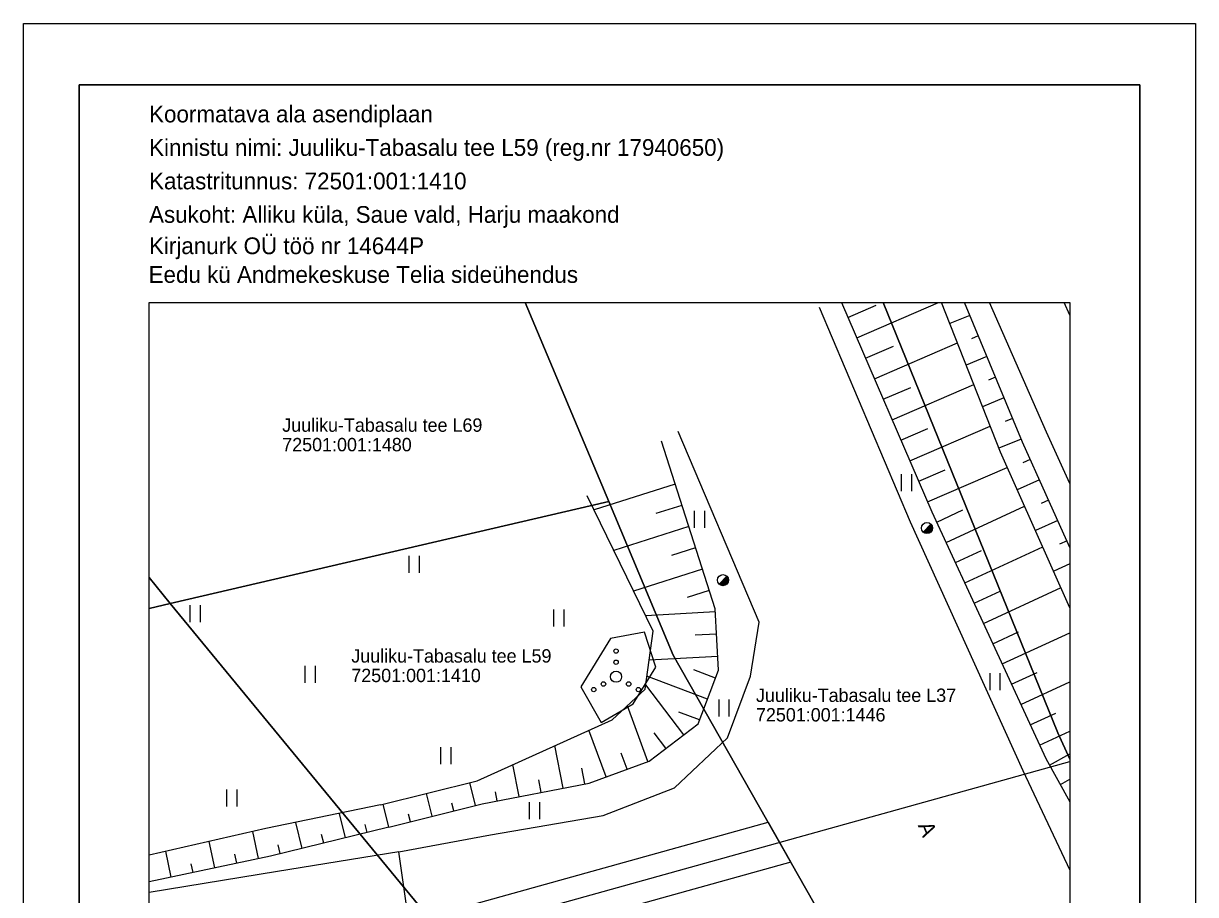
# Model space of a CAD drawing. Extents: x 533265.2 to 533317.7, y 6581481.2 to 6581555.4.
# Drawn here: x 533265.2 to 533317.7, y 6581516.4 to 6581555.4 of the extents above; entities that cross this region are included whole.
import ezdxf

# ---------------------------------------------------------------- set-up
doc = ezdxf.new("R2010")
doc.units = 0
for name, color, linetype in [('HALJASTUS', 7, 'Continuous'), ('KASUTUSALA', 7, 'Continuous'), ('PIIR', 7, 'Continuous'), ('POST', 7, 'Continuous'), ('PR_SIDE', 7, 'Continuous'), ('RELJEEF', 7, 'Continuous'), ('TEE', 7, 'Continuous'), ('VORMISTUS', 7, 'Continuous')]:
    doc.layers.add(name, color=color, linetype=linetype)

msp = doc.modelspace()

# ---------------------------------------------------------------- linework, layer by layer
at = {"layer": 'HALJASTUS'}
for p, q in [((533304.51, 6581535.234), (533304.51, 6581534.473)), ((533304.966, 6581535.234), (533304.966, 6581534.473)), ((533295.237, 6581533.587), (533295.237, 6581532.826)), ((533295.692, 6581533.587), (533295.692, 6581532.826)), ((533282.457, 6581531.581), (533282.457, 6581530.82)), ((533282.912, 6581531.581), (533282.912, 6581530.82)), ((533272.65, 6581529.364), (533272.65, 6581528.603)), ((533273.105, 6581529.364), (533273.105, 6581528.603)), ((533288.939, 6581529.174), (533288.939, 6581528.413)), ((533289.394, 6581529.174), (533289.394, 6581528.413)), ((533277.798, 6581526.641), (533277.798, 6581525.879)), ((533278.253, 6581526.641), (533278.253, 6581525.879)), ((533308.477, 6581526.324), (533308.477, 6581525.563)), ((533308.932, 6581526.324), (533308.932, 6581525.563)), ((533296.334, 6581525.141), (533296.334, 6581524.38)), ((533296.789, 6581525.141), (533296.789, 6581524.38)), ((533283.875, 6581523.009), (533283.875, 6581522.248)), ((533284.33, 6581523.009), (533284.33, 6581522.248)), ((533274.295, 6581521.109), (533274.295, 6581520.347)), ((533274.751, 6581521.109), (533274.751, 6581520.347)), ((533287.852, 6581520.539), (533287.852, 6581519.777)), ((533288.307, 6581520.539), (533288.307, 6581519.777))]:
    msp.add_line(p, q, dxfattribs=at)
msp.add_lwpolyline([(533292.5, 6581524.94), (533293.512, 6581526.593), (533293.016, 6581528.153), (533291.487, 6581527.871), (533290.163, 6581525.701), (533291.07, 6581524.104), (533292.5, 6581524.94)], dxfattribs=at)
for centre, radius in [((533291.738, 6581527.309), 0.1), ((533291.738, 6581526.809), 0.1), ((533291.738, 6581526.159), 0.25), ((533290.738, 6581525.584), 0.1), ((533291.173, 6581525.834), 0.1), ((533292.303, 6581525.834), 0.1), ((533292.738, 6581525.584), 0.1)]:
    msp.add_circle(centre, radius, dxfattribs=at)
at = {"layer": 'KASUTUSALA'}
msp.add_lwpolyline([(533298.55, 6581519.64), (533299.566, 6581517.847), (533284.712, 6581513.713), (533283.321, 6581515.401)], close=True, dxfattribs=at)
at = {"layer": 'PIIR'}
for points in [[(533287.673, 6581542.926), (533291.41, 6581534.01), (533271.76, 6581529.44), (533270.819, 6581530.608)], [(533312.069, 6581495.797), (533303.4, 6581511.09), (533294.3, 6581527.13), (533291.41, 6581534.01), (533287.673, 6581542.926)], [(533312.069, 6581522.468), (533311.52, 6581523.65), (533303.707, 6581542.926)], [(533303.707, 6581542.926), (533311.52, 6581523.65), (533312.069, 6581522.468)], [(533270.819, 6581530.608), (533271.76, 6581529.44), (533270.819, 6581529.221)], [(533270.819, 6581529.221), (533271.76, 6581529.44), (533289.68, 6581507.68), (533270.819, 6581503.146)]]:
    msp.add_lwpolyline(points, dxfattribs=at)
msp.add_lwpolyline([(533291.41, 6581534.01), (533294.3, 6581527.13), (533303.4, 6581511.09), (533289.68, 6581507.68), (533271.76, 6581529.44)], close=True, dxfattribs=at)
at = {"layer": 'POST'}
for p, q in [((533305.487, 6581532.643), (533305.84, 6581532.997)), ((533296.35, 6581530.309), (533296.704, 6581530.663))]:
    msp.add_line(p, q, dxfattribs=at)
for centre in [(533305.664, 6581532.82), (533296.527, 6581530.486)]:
    msp.add_circle(centre, 0.25, dxfattribs=at)
for centre, radius, start, end in [((533305.664, 6581532.82), 0.225, 224.8541, 45.0356), ((533305.664, 6581532.82), 0.2, 224.8427, 45.047), ((533305.664, 6581532.82), 0.175, 224.8281, 45.0616), ((533305.664, 6581532.82), 0.15, 224.8087, 45.081), ((533305.664, 6581532.82), 0.125, 224.7814, 45.1083), ((533305.664, 6581532.82), 0.1, 224.7406, 45.1491), ((533305.664, 6581532.82), 0.075, 224.6725, 45.2172), ((533305.664, 6581532.82), 0.05, 224.5363, 45.3534), ((533305.664, 6581532.82), 0.025, 224.1278, 45.7619), ((533296.527, 6581530.486), 0.225, 224.8541, 45.0356), ((533296.527, 6581530.486), 0.2, 224.8427, 45.047), ((533296.527, 6581530.486), 0.175, 224.8281, 45.0616), ((533296.527, 6581530.486), 0.15, 224.8087, 45.081), ((533296.527, 6581530.486), 0.125, 224.7814, 45.1083), ((533296.527, 6581530.486), 0.1, 224.7406, 45.1491), ((533296.527, 6581530.486), 0.075, 224.6725, 45.2172), ((533296.527, 6581530.486), 0.05, 224.5363, 45.3534), ((533296.527, 6581530.486), 0.025, 224.1278, 45.7619)]:
    msp.add_arc(centre, radius, start, end, dxfattribs=at)
at = {"layer": 'PR_SIDE'}
msp.add_line((533270.819, 6581510.884), (533312.069, 6581522.365), dxfattribs=at)
at = {"layer": 'RELJEEF'}
for p, q in [((533302.12, 6581542.26), (533303.39, 6581542.809)), ((533302.517, 6581541.343), (533306.181, 6581542.926)), ((533307.579, 6581542.349), (533306.687, 6581541.979)), ((533307.963, 6581541.426), (533307.66, 6581541.3)), ((533302.914, 6581540.425), (533304.163, 6581540.965)), ((533303.31, 6581539.507), (533307.028, 6581541.114)), ((533308.346, 6581540.502), (533307.42, 6581540.118)), ((533304.104, 6581537.671), (533307.761, 6581539.251)), ((533308.729, 6581539.578), (533308.414, 6581539.448)), ((533303.707, 6581538.589), (533304.936, 6581539.12)), ((533309.112, 6581538.654), (533308.152, 6581538.256)), ((533309.495, 6581537.731), (533309.169, 6581537.596)), ((533304.5, 6581536.753), (533305.709, 6581537.275)), ((533304.897, 6581535.835), (533308.493, 6581537.389)), ((533309.878, 6581536.807), (533308.884, 6581536.395)), ((533305.691, 6581533.999), (533309.257, 6581535.54)), ((533310.286, 6581535.894), (533309.957, 6581535.745)), ((533305.294, 6581534.917), (533306.482, 6581535.431)), ((533310.698, 6581534.983), (533309.707, 6581534.534)), ((533294.387, 6581534.789), (533290.751, 6581533.629)), ((533311.111, 6581534.072), (533310.779, 6581533.922)), ((533294.691, 6581533.837), (533293.526, 6581533.465)), ((533306.099, 6581533.086), (533307.275, 6581533.629)), ((533306.518, 6581532.179), (533310.034, 6581533.802)), ((533294.995, 6581532.884), (533291.639, 6581531.813)), ((533311.523, 6581533.161), (533310.523, 6581532.708)), ((533295.299, 6581531.931), (533294.227, 6581531.589)), ((533306.938, 6581531.271), (533308.106, 6581531.81)), ((533307.357, 6581530.363), (533310.85, 6581531.976)), ((533311.936, 6581532.25), (533311.601, 6581532.099)), ((533295.603, 6581530.979), (533292.526, 6581529.997)), ((533312.069, 6581531.213), (533311.34, 6581530.883)), ((533295.907, 6581530.026), (533294.928, 6581529.714)), ((533307.776, 6581529.455), (533308.937, 6581529.991)), ((533308.196, 6581528.547), (533311.667, 6581530.15)), ((533296.18, 6581529.068), (533293.066, 6581528.892)), ((533308.615, 6581527.639), (533309.768, 6581528.172)), ((533309.034, 6581526.731), (533312.069, 6581528.133)), ((533296.236, 6581528.069), (533295.277, 6581528.015)), ((533296.292, 6581527.071), (533293.22, 6581526.897)), ((533295.836, 6581525.161), (533293.123, 6581526.188)), ((533296.19, 6581526.097), (533295.214, 6581526.466)), ((533309.454, 6581525.824), (533310.6, 6581526.353)), ((533294.766, 6581523.561), (533293.069, 6581525.796)), ((533309.873, 6581524.916), (533312.069, 6581525.93)), ((533293.166, 6581522.365), (533292.244, 6581524.862)), ((533295.482, 6581524.226), (533294.554, 6581524.577)), ((533310.292, 6581524.008), (533311.431, 6581524.534)), ((533291.29, 6581521.672), (533290.518, 6581523.761)), ((533293.97, 6581522.956), (533293.449, 6581523.642)), ((533310.711, 6581523.1), (533312.069, 6581523.727)), ((533289.362, 6581521.166), (533288.994, 6581523.073)), ((533292.228, 6581522.018), (533291.963, 6581522.736)), ((533311.153, 6581522.203), (533312.069, 6581522.712)), ((533287.398, 6581520.787), (533287.12, 6581522.228)), ((533290.344, 6581521.355), (533290.206, 6581522.069)), ((533285.438, 6581520.391), (533285.182, 6581521.419)), ((533288.38, 6581520.976), (533288.272, 6581521.534)), ((533311.638, 6581521.329), (533312.069, 6581521.568)), ((533283.497, 6581519.908), (533283.242, 6581520.934)), ((533286.416, 6581520.597), (533286.339, 6581521)), ((533281.557, 6581519.424), (533281.301, 6581520.448)), ((533284.468, 6581520.149), (533284.382, 6581520.492)), ((533279.614, 6581518.948), (533279.347, 6581520.039)), ((533282.527, 6581519.666), (533282.442, 6581520.008)), ((533275.725, 6581518.013), (533275.469, 6581519.226)), ((533277.672, 6581518.472), (533277.387, 6581519.634)), ((533280.585, 6581519.186), (533280.499, 6581519.538)), ((533273.768, 6581517.6), (533273.519, 6581518.783)), ((533278.643, 6581518.71), (533278.551, 6581519.085)), ((533271.811, 6581517.187), (533271.568, 6581518.341)), ((533274.747, 6581517.806), (533274.662, 6581518.206)), ((533276.7, 6581518.234), (533276.603, 6581518.633)), ((533272.79, 6581517.393), (533272.708, 6581517.783)), ((533270.833, 6581516.98), (533270.819, 6581517.047))]:
    msp.add_line(p, q, dxfattribs=at)
for points in [[(533301.832, 6581542.926), (533305.883, 6581533.554), (533310.992, 6581522.492), (533312.069, 6581520.555)], [(533312.069, 6581529.252), (533308.956, 6581536.213), (533306.315, 6581542.926)], [(533312.069, 6581531.956), (533309.937, 6581536.665), (533307.34, 6581542.926)], [(533281.557, 6581519.424), (533285.742, 6581520.467), (533290.534, 6581521.392), (533293.214, 6581522.382), (533295.418, 6581524.056), (533296.327, 6581526.46), (533296.172, 6581529.195), (533293.772, 6581536.719)], [(533281.183, 6581520.419), (533285.51, 6581521.501), (533291.561, 6581524.231), (533293.042, 6581525.599), (533293.4, 6581528.208), (533290.443, 6581534.26)], [(533281.183, 6581520.419), (533276.051, 6581519.358), (533270.819, 6581518.171)], [(533281.557, 6581519.424), (533276.261, 6581518.126), (533270.819, 6581516.978)]]:
    msp.add_lwpolyline(points, dxfattribs=at)
at = {"layer": 'TEE'}
msp.add_line((533312.069, 6581542.35), (533311.816, 6581542.926), dxfattribs=at)
for points in [[(533312.069, 6581534.817), (533311.019, 6581537.113), (533308.471, 6581542.926)], [(533300.834, 6581542.715), (533304.915, 6581533.103), (533309.953, 6581521.952), (533312.069, 6581517.5)], [(533312.069, 6581499.932), (533309.623, 6581504.459), (533306.388, 6581511.03), (533305.005, 6581512.072), (533302.788, 6581513.446), (533299.515, 6581514.457), (533295.949, 6581515.216), (533292.859, 6581515.08), (533287.545, 6581514.499), (533282.671, 6581513.706), (533282.015, 6581518.32), (533286.115, 6581519.072), (533291.163, 6581519.939), (533294.36, 6581521.188), (533296.727, 6581523.417), (533297.752, 6581526.189), (533298.149, 6581528.6), (533294.521, 6581537.152)], [(533282.015, 6581518.32), (533276.572, 6581517.43), (533270.819, 6581516.487)]]:
    msp.add_lwpolyline(points, dxfattribs=at)
at = {"layer": 'VORMISTUS'}
for points in [[(533265.194, 6581555.426), (533317.694, 6581555.426), (533317.694, 6581481.176), (533265.194, 6581481.176)], [(533267.694, 6581483.926), (533315.194, 6581483.926), (533315.194, 6581552.676), (533267.694, 6581552.676)], [(533267.694, 6581552.676), (533315.194, 6581552.676), (533315.194, 6581483.926), (533267.694, 6581483.926)], [(533312.069, 6581490.426), (533270.819, 6581490.426), (533270.819, 6581542.926), (533312.069, 6581542.926)]]:
    msp.add_lwpolyline(points, close=True, dxfattribs=at)

# ---------------------------------------------------------------- texts
at = {"layer": 'PIIR'}
for s, p in [('Juuliku-Tabasalu tee L69', (533276.785, 6581537.133)), ('72501:001:1480', (533276.785, 6581536.258)), ('Juuliku-Tabasalu tee L59', (533279.879, 6581526.793)), ('72501:001:1410', (533279.879, 6581525.918)), ('Juuliku-Tabasalu tee L37', (533298.004, 6581525.03)), ('72501:001:1446', (533298.004, 6581524.155))]:
    msp.add_text(s, height=0.6, dxfattribs=at).set_placement(p)
at = {"layer": 'TEE'}
msp.add_text('A', height=0.7, rotation=292.1583, dxfattribs=at).set_placement((533305.248, 6581519.498))
at = {"layer": 'VORMISTUS'}
for s, p in [('Koormatava ala asendiplaan', (533270.821, 6581550.994)), ('Kinnistu nimi: Juuliku-Tabasalu tee L59 (reg.nr 17940650)', (533270.821, 6581549.494)), ('Katastritunnus: 72501:001:1410', (533270.821, 6581547.994)), ('Asukoht: Alliku küla, Saue vald, Harju maakond', (533270.821, 6581546.494))]:
    msp.add_text(s, height=0.75, dxfattribs=at).set_placement(p)
for s, p in [('Kirjanurk OÜ töö nr 14644P', (533270.818, 6581545.091)), ('Eedu kü Andmekeskuse Telia sideühendus', (533270.799, 6581543.804))]:
    msp.add_text(s, height=0.75, rotation=360, dxfattribs=at).set_placement(p)

doc.saveas('drawing.dxf')
